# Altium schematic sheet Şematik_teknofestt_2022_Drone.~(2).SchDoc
size A4; SheetNumber: 1; SheetTotal: 1
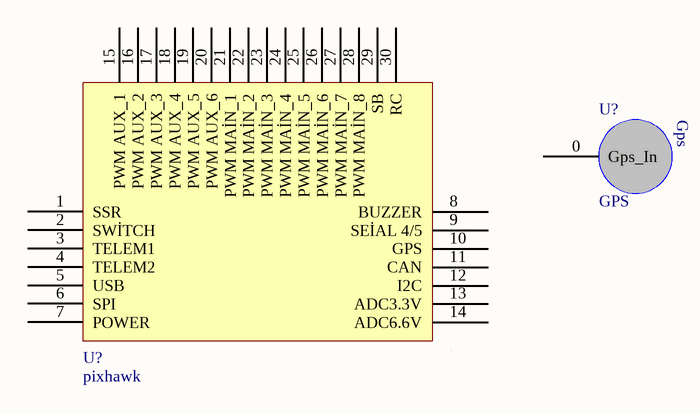
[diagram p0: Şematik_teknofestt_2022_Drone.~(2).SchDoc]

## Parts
(Parts that share a designator on the sheet are numbered #1, #2 ... from top to bottom, then left to right.)
U?#1  pixhawk
U?#2  GPS

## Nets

Not connected (* = marked no-connect by the designer): U?#1 1(SSR) 2(SWİTCH) 3(TELEM1) 4(TELEM2) 5(USB) 6(SPI) 7(POWER) 8(BUZZER) 9(SEİAL_4/5) 10(GPS) 11(CAN) 12(I2C) 13(ADC3.3V) 14(ADC6.6V) 15(PWM_AUX_1) 16(PWM_AUX_2) 17(PWM_AUX_3) 18(PWM_AUX_4) 19(PWM_AUX_5) 20(PWM_AUX_6) 21(PWM_MAİN_1) 22(PWM_MAİN_2) 23(PWM_MAİN_3) 24(PWM_MAİN_4) 25(PWM_MAİN_5) 26(PWM_MAİN_6) 27(PWM_MAİN_7) 28(PWM_MAİN_8) 29(SB) 30(RC); U?#2 0(Gps_In)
